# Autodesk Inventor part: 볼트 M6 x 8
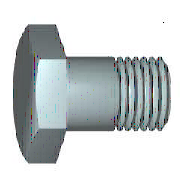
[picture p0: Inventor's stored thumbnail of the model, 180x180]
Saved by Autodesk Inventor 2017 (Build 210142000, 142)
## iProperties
Created: 2012-02
Part Number: 볼트 M6 x 8
Material: 강철, 연강
Description: 6각 머리 볼트 및 6각 머리 나사
Document SubType Name: Modeling
Standard: KS B 1002
Designer: mduedu
Standards Organization: KS
Language: ko-KR
Size Designation: C  M 6 x 12
Categories: <MemberInstance><Categories><Category DisplayName="조임쇠" InternalName="e4da775c-781d-43d5-af7c-5136215cf5a6" Mnemonic="FSTN"><Category DisplayName="볼트" InternalN
Density: 7.86 g/cm^3
Mass: 4.46616 g
Surface Area: 4.51243 cm^2
Volume: 0.568214 cm^3
Appearance: 강철
IsCustomPart: 1
Author: mduedu
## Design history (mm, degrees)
sketch "스케치1"
  geometry: L1 (0, 3)-(8, 3); L2 (8, 3)-(8, 0); L3 (8, 0)-(0, 0); L4 (-2.4, 0)-(14.4, 0) reference; L5 (0, -0.6)-(0, 3.6) reference; L6 (0, 3)-(0, 0)
  constraints: 8 end point, 3 point on line, 1 collinear
  dimensions: "d2" = 6 diameter of L1 L3 (= GD); "d59" = 8 distance between parallel lines of L2 L5 (= NLG)
revolve "본체" sketch "스케치1" stored, may be unused: angle "d12" = 90 deg
sketch "스케치2"
  geometry: L1 (0, 5.774)-(5, 2.887); L2 (5, 2.887)-(5, -2.887); L3 (5, -2.887)-(0, -5.774); L4 (0, -5.774)-(-5, -2.887); L5 (-5, -2.887)-(-5, 2.887); L6 (-5, 2.887)-(0, 5.774); L7 (-7, 0)-(7, 0) reference; L8 (0, 8.083)-(0, -8.083) reference; 2 further points
  constraints: 12 end point, 2 midpoint, 1 coincident, 1 vertical, 11 other
  dimensions: "d11" = 10 distance between parallel lines of L5 L2 (= SW)
extrude "머리" join sketch "스케치2" distance "d3" = 4 (= KOH); taper "d4" = 0 deg
revolve "모따기1" stored, may be unused: angle "d21" = 90 deg
workplane "Work Plane1"
body "Solid1"
feature "스레드" dims "d15" = 9 (= GEL), "d16" = 0
chamfer "모따기2" distance "d6" = 0.61345 (= -0.5 x SPD + 0.5 x GD); stored, may be unused: second distance "d7" = 0.61355 (computed from GUL), angle "d55" = 45 deg
sketch "스케치4"
  geometry: L1 (-3.423, 6)-(-4, 5); L2 (-1.1, 0)-(-0.234, 0); L3 (-4.753, 0)-(0.519, 0) reference; L4 (-4, 6)-(-3.423, 6); L5 (-4, 5)-(-4, 6); L6 (0, 7.2)-(0, -1.2) reference
  constraints: 8 end point, 1 parallel, 1 perpendicular, 1 point on line
  dimensions: "d65" = 10 diameter of L1.end L2 (= SW); "d67" = 30 deg angle of L1 L5 (= ANG1); "d68" = 12 diameter of L4 L2 (= 1.2 x SW); "d69" = 4 distance between parallel lines of L5 L6 (= KOH)
other parameters: "NLG" = 8 [user parameter; used in 1 equation term], "GD" = 6 (= NND) [user parameter; used in 2 equation terms], "BDM" = 6 (= NND) [user parameter], "KOH" = 4 [user parameter; used in 2 equation terms], "GEL" = 9 [user parameter; used in 1 equation term], "SW" = 10 [user parameter; used in 5 equation terms], "SPD" = 4.7731 (= NND - 1.2269 x PTC) [user parameter; used in 1 equation term], "SD2" = 6 (= NND) [user parameter], "SD" = 0 [user parameter], "ANG1" = 30 deg [user parameter; used in 1 equation term], "GAL" = 0.61345 (= 0.61345 x PTC) [user parameter], "GUL" = 0.61345 (= 0.61345 x PTC) [user parameter; used in 1 equation term], "d8" = 0, "RR" = 0.25 [user parameter], "d58" = 0, "RR1" = 0.1 [user parameter], "GD1" = 4.7731 (= THREADDIA - 1.2269 x PTC) [user parameter], "THREADDIA" = 6 [user parameter; used in 1 equation term], "TOA" = 30 deg [user parameter], "PTC" = 1 [user parameter; used in 5 equation terms], "NND" = 6 [user parameter; used in 4 equation terms], "E0" = 11.55 (= 1.155 x SW) [user parameter]
